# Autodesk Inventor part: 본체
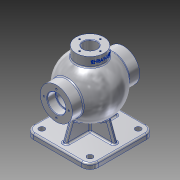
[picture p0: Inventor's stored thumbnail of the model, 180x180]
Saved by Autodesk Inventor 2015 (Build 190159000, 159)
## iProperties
Created: 2025-08
Part Number: 본체
Material: 알루미늄 6061
Document SubType Name: Modeling
Designer: user
Density: 2.7 g/cm^3
Appearance: 알루미늄 - 평지
Mass: 1526.79 g
Surface Area: 1175.06 cm^2
Volume: 565.478 cm^3
Author: user
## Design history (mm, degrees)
sketch "스케치1"
  geometry: L1 (-62.5, 62.5)-(62.5, 62.5); L2 (62.5, 62.5)-(62.5, -62.5); L3 (62.5, -62.5)-(-62.5, -62.5); L4 (-62.5, -62.5)-(-62.5, 62.5); 3 further points
  constraints: 8 end point, 2 midpoint, 2 parallel, 1 horizontal, 1 horizontal alignment, 1 perpendicular, 1 vertical alignment
  dimensions: "d0" = 125 distance of L2.end L3.end; "d1" = 125 distance of L1.end L2.end
extrude "돌출1" new body sketch "스케치1" distance "d2" = 10; taper "d3" = 0 deg
node "작업 평면1"
sketch "스케치3"
  geometry: L1 (54, 0)-(44, 0); L2 (-44, 0)-(-54, 0); A1 r 54 centre (0, 0) between (-54, 0) and (54, 0); A2 r 44 centre (0, 0) between (-44, 0) and (44, 0); 1 further point
  constraints: 4 end point, 4 point on circle, 2 centre point, 2 coincident, 2 horizontal
  dimensions: "d9" = 108 diameter of A1; "d10" = 88 diameter of A2; "d11" = 108 distance of L1.start L2.end; "d12" = 10 distance of L2.start L2.end
revolve "회전2" sketch "스케치3" stored, may be unused: angle "d13" = 90 deg
sketch "스케치4"
  geometry: L1 (4, -50.5)-(-4, -50.5); L2 (-4, -50.5)-(-4, 50.5); L3 (-4, 50.5)-(4, 50.5); L4 (4, 50.5)-(4, -50.5); L5 (50.5, -4)-(-50.5, -4); L6 (-50.5, -4)-(-50.5, 4); L7 (-50.5, 4)-(50.5, 4); L8 (50.5, 4)-(50.5, -4); L9 (62.5, 62.5)-(62.5, -62.5) reference; L10 (-62.5, -62.5)-(-62.5, 62.5) reference; L11 (62.5, -62.5)-(-62.5, -62.5) reference; L12 (-62.5, 62.5)-(62.5, 62.5) reference; 3 further points
  constraints: 16 end point, 4 parallel, 2 horizontal, 2 midpoint, 2 perpendicular, 1 horizontal alignment, 1 vertical alignment
  dimensions: "d14" = 8 distance of L1.start L1.end; "d15" = 8 distance of L5.end L6.end; "d16" = 12 distance between parallel lines of L9 L8; "d17" = 12 distance between parallel lines of L10 L6; "d18" = 12 distance between parallel lines of L11 L1; "d19" = 12 distance between parallel lines of L12 L3
extrude "돌출2" join sketch "스케치4" stored distance "d20" = 10; taper "d21" = 0 deg
feature "면 기울기1" dims angle "d22" = 20 deg
feature "면 기울기2" dims angle "d23" = 20 deg
feature "면 기울기3" dims angle "d24" = 20 deg
feature "면 기울기4" dims angle "d25" = 20 deg
node "작업 평면3"
sketch "스케치5"
  geometry: L1 (37.329, 46.186)-(37.329, 46.186) reference; L2 (4, 31.297)-(4, 46.186) reference; L3 (-4, 46.186)-(-4, 31.297) reference; L4 (-37.329, 46.186)-(-37.329, 46.186) reference; L5 (-4, 31.297)-(-4, 46.186) reference; L6 (4, 46.186)-(4, 31.297) reference; C1 r 31 at (0, 85); A1 r 53.852 centre (0, 85) between (4, 31.297) and (37.329, 46.186) reference; A2 r 53.852 centre (0, 85) between (-37.329, 46.186) and (-4, 31.297) reference; A3 r 53.852 centre (0, 85) between (-37.329, 46.186) and (-4, 31.297) reference; A4 r 53.852 centre (0, 85) between (4, 31.297) and (37.329, 46.186) reference; 3 further points; 2 other entities
  constraints: 1 centre point, 1 coincident, 2 other
  dimensions: "d28" = 62 diameter of C1
extrude "돌출3" join sketch "스케치5" stored distance "d29" = 10; taper "d30" = 0 deg
hole "구멍1" diameter "d33" = 30; stored, may be unused: countersink angle "d37" = 90 deg, drill point angle "d39" = 0 deg; dims "d34" = 6, "d35" = 35, "d36" = 16, "d38" = 65, "d40" = 10, "d41" = 10
node "작업 평면4"
sketch "스케치6"
  geometry: C1 r 27 at (0, 0); 1 further point
  constraints: 1 centre point, 1 coincident
  dimensions: "d43" = 54 diameter of C1
extrude "돌출4" join sketch "스케치6" stored distance "d44" = 10; taper "d45" = 0 deg
hole "구멍2" diameter "d48" = 26; stored, may be unused: countersink angle "d52" = 90 deg, drill point angle "d54" = 0 deg; dims "d46" = 10, "d47" = 10, "d49" = 6, "d50" = 35, "d51" = 16, "d53" = 8
fillet "모깎기1" dims "d55" = 16
hole "구멍3" diameter "d58" = 11; stored, may be unused: countersink angle "d62" = 90 deg, drill point angle "d64" = 0 deg; dims "d56" = 10, "d57" = 10, "d59" = 6, "d60" = 35, "d61" = 16, "d63" = 8
node "작업 평면5"
sketch "스케치7"
  geometry: L1 (-27, 131.765)-(27, 131.765) reference; L2 (-27, 150)-(27, 150) reference; L3 (-27, 150)-(-27, 131.765) reference; L4 (13, 127.036)-(-13, 127.036) reference; L5 (41.364, 70)-(41.364, 100) reference; L6 (-41.364, 100)-(-41.364, 70) reference; A1 r 54 centre (0, 85) between (37.385, 46.034) and (-37.385, 46.034) reference; 2 further points
  constraints: 1 vertical alignment, 1 other
  dimensions: "d73" = 9 distance from line of L2 point (0, 141)
feature "엠보싱1" sketch "스케치7" dims "d14" = 8, "d18" = 12, "d19" = 12, "d74" = 1, "d75" = 0
sketch "스케치8"
  geometry: L1 (0, 0)-(0, 24); A1 r 54 centre (0, 0) between (37.385, -38.966) and (-37.385, -38.966) reference; 1 further point
  constraints: 2 end point, 1 vertical
  dimensions: "d76" = 24 distance of L1.start L1.end
hole "구멍4" sketch "스케치8" at (0, 24) diameter "d77" = 3.242; stored, may be unused: countersink angle "d81" = 90 deg, drill point angle "d83" = 118 deg; dims "d78" = 12, "d79" = 35, "d80" = 16, "d82" = 15
sketch "스케치9"
  geometry: L1 (0, 0)-(0, 20); C1 r 27 at (0, 0) reference; 1 further point
  constraints: 2 end point, 1 vertical
  dimensions: "d87" = 20 distance of L1.start L1.end
hole "구멍5" sketch "스케치9" at (0, 20) diameter "d88" = 3.242; stored, may be unused: countersink angle "d92" = 90 deg, drill point angle "d94" = 118 deg; dims "d89" = 9, "d90" = 35, "d91" = 16, "d93" = 11
fillet "모깎기2" dims "d98" = 0.6
chamfer "모따기1" distance "d99" = 1; stored, may be unused: second distance "d100" = 2, angle "d101" = 45 deg
fillet "모깎기3" dims "d102" = 3
fillet "모깎기4" dims "d103" = 3
fillet "모깎기5" dims "d104" = 3
node "솔리드1"
mirror "대칭1"
pattern_linear "직사각형 패턴1" dims "d67" = 93, "d70" = 93
pattern_circular "원형 패턴1" dims angle "d85" = 360 deg
mirror "대칭2"
pattern_circular "원형 패턴2" dims angle "d96" = 360 deg
node "투영된 루프1"
node "투영된 루프2"
node "투영된 루프3"
other parameters: "d4" = 85, "d27" = -65, "d71" = 13
